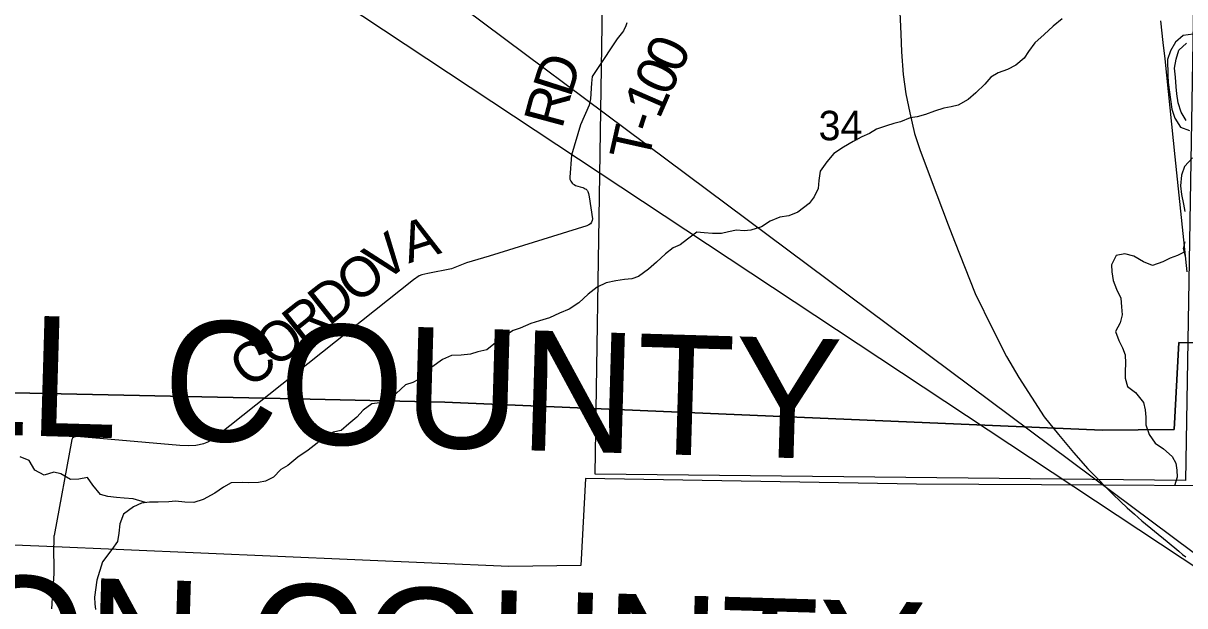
# Model space of a CAD drawing. Extents: x -19.9 to 41.9, y 0 to 32.3.
# Drawn here: x 3.386 to 5.034, y 17.59 to 18.417 of the extents above; entities that cross this region are included whole.
import ezdxf

# ---------------------------------------------------------------- set-up
doc = ezdxf.new("R2010")
doc.units = 0
for name, color, linetype in [('GM_X_Corporation', 7, 'Continuous'), ('GM_X_County', 7, 'Continuous'), ('GM_X_County_Text', 7, 'Continuous'), ('GM_X_Major_River', 7, 'Continuous'), ('GM_X_Minor_River', 7, 'Continuous'), ('GM_X_Rail_Line', 7, 'Continuous'), ('GM_X_Section', 7, 'Continuous'), ('GM_X_Section_Text', 7, 'Continuous'), ('GM_X_State_Route', 7, 'Continuous'), ('GM_X_Township_Road', 7, 'Continuous'), ('GM_X_Township_Road_Text', 7, 'Continuous'), ('SH_Text', 7, 'Continuous')]:
    doc.layers.add(name, color=color, linetype=linetype)

msp = doc.modelspace()

# ---------------------------------------------------------------- linework, layer by layer
at = {"layer": 'GM_X_Corporation'}
for points in [[(8.9, 17.8974), (8.9, 20.9), (2.1, 20.9), (2.1, 17.918), (2.4715, 17.9106), (2.973, 17.9007), (3.7505, 17.884), (3.984, 17.879), (4.2613, 17.8672), (4.9169, 17.8392), (5.0192, 17.8403), (5.0257, 17.9637), (5.4954, 17.9559), (5.761, 17.9543), (5.9048, 17.9534), (6.2397, 17.9517), (6.2497, 17.9517), (6.3069, 17.9505), (6.7, 17.9422), (6.9468, 17.937), (7.3858, 17.9277), (7.5529, 17.9242), (7.9072, 17.9171)], [(2.1, 17.918), (2.1, 14.1), (8.9, 14.1), (8.9, 17.8974), (7.9072, 17.9171), (7.5529, 17.9242), (7.3858, 17.9277), (6.9468, 17.937), (6.7, 17.9422), (6.3069, 17.9505), (6.2497, 17.9517), (6.2397, 17.9517), (5.9048, 17.9534), (5.761, 17.9543), (5.4954, 17.9559), (5.0257, 17.9637), (5.0192, 17.8403), (4.9169, 17.8392), (4.2613, 17.8672), (3.984, 17.879), (3.7505, 17.884), (2.973, 17.9007), (2.4715, 17.9106)]]:
    msp.add_lwpolyline(points, close=True, dxfattribs=at)
for points in [[(2.973, 17.9007), (3.7505, 17.884), (3.984, 17.879), (4.2613, 17.8672), (4.9169, 17.8392), (5.0192, 17.8403), (5.0257, 17.9637), (5.4954, 17.9559), (5.761, 17.9543), (5.9048, 17.9534), (6.2397, 17.9517), (6.2497, 17.9517), (6.3069, 17.9505), (6.7, 17.9422), (6.9468, 17.937), (7.3858, 17.9277), (7.5529, 17.9242), (7.9072, 17.9171), (7.9208, 18.3004), (7.9387, 18.9418), (7.9433, 19.1981), (7.9567, 19.9408), (7.9833, 20.9), (2.1, 20.9)], [(7.9012, 17.4524), (7.9072, 17.9171), (7.5529, 17.9242), (7.3858, 17.9277), (6.9468, 17.937), (6.7, 17.9422), (6.3069, 17.9505), (6.2497, 17.9517), (6.2397, 17.9517), (5.9048, 17.9534), (5.761, 17.9543), (5.4954, 17.9559), (5.0257, 17.9637), (5.0192, 17.8403), (4.9169, 17.8392), (4.2613, 17.8672), (3.984, 17.879), (3.7505, 17.884), (2.973, 17.9007), (2.4715, 17.9106), (2.1, 17.918), (2.1, 14.1)]]:
    msp.add_lwpolyline(points, dxfattribs=at)
at = {"layer": 'GM_X_County'}
msp.add_lwpolyline([(8.9, 17.6915), (8.8006, 17.694), (8.0736, 17.7036), (7.0652, 17.7237), (6.7109, 17.7307), (6.5438, 17.7343), (6.1048, 17.7436), (5.8581, 17.7488), (5.4649, 17.757), (5.4078, 17.7582), (5.3977, 17.7582), (5.0628, 17.7599), (4.9191, 17.7608), (4.6534, 17.7624), (4.1838, 17.7703), (4.1772, 17.6468), (4.0749, 17.6457), (3.4193, 17.6737), (3.142, 17.6855), (2.9085, 17.6906), (2.1311, 17.7073), (2.1, 17.7079)], dxfattribs=at)
at = {"layer": 'GM_X_Major_River'}
for points in [[(5.0461, 18.4016), (5.032, 18.3995), (5.0212, 18.3902), (5.0138, 18.3779), (5.0098, 18.3657), (5.0101, 18.3433), (5.0107, 18.3331), (5.0141, 18.3088), (5.0159, 18.2952), (5.0199, 18.282), (5.0281, 18.2696), (5.0407, 18.2649)], [(5.0359, 18.2788), (5.0289, 18.2909), (5.0249, 18.3041), (5.0231, 18.3166), (5.0218, 18.3268), (5.0208, 18.3404), (5.0195, 18.3533), (5.0219, 18.3659), (5.0255, 18.3789), (5.0364, 18.3889)], [(5.0451, 18.2258), (5.0339, 18.2135), (5.0296, 18.2013), (5.0283, 18.1861), (5.0293, 18.174), (5.0325, 18.1603), (5.0342, 18.1497)], [(5.0342, 18.1068), (5.0317, 18.0973), (5.0349, 18.086)]]:
    msp.add_lwpolyline(points, dxfattribs=at)
at = {"layer": 'GM_X_Minor_River'}
for points in [[(4.8604, 18.4235), (4.8476, 18.4128), (4.8348, 18.4009), (4.8216, 18.3894), (4.8122, 18.3768), (4.8062, 18.3672), (4.7945, 18.3573), (4.7828, 18.3515), (4.7692, 18.3464), (4.7589, 18.3406), (4.7503, 18.3303), (4.7375, 18.3184), (4.7266, 18.3085), (4.7126, 18.3008), (4.7027, 18.2984), (4.6921, 18.2964), (4.6788, 18.2921), (4.6663, 18.2875), (4.6542, 18.2843), (4.6447, 18.2827), (4.6307, 18.2769), (4.6213, 18.2746), (4.611, 18.2711), (4.5966, 18.2668), (4.5868, 18.2606), (4.5758, 18.2556), (4.5634, 18.249), (4.5498, 18.2409), (4.5362, 18.2321), (4.526, 18.2202), (4.517, 18.2069), (4.5148, 18.1939), (4.5138, 18.1822), (4.5082, 18.1707), (4.5011, 18.1608), (4.4852, 18.1489), (4.4723, 18.1435), (4.4594, 18.1414), (4.4458, 18.136), (4.4333, 18.1279), (4.4186, 18.1233), (4.4091, 18.1224), (4.3981, 18.1231), (4.3867, 18.1207), (4.3768, 18.1183), (4.3639, 18.1186), (4.3521, 18.1193), (4.3419, 18.1203), (4.3287, 18.1103), (4.3181, 18.1023), (4.3083, 18.098), (4.2973, 18.0896), (4.2845, 18.0777), (4.2732, 18.0677), (4.2592, 18.0574), (4.2494, 18.0542), (4.2391, 18.053), (4.2266, 18.051), (4.2133, 18.0482), (4.2001, 18.042), (4.1876, 18.0324), (4.1741, 18.0198), (4.1605, 18.0109), (4.1468, 18.0051), (4.1325, 17.9989), (4.1185, 17.9943), (4.106, 17.9904), (4.0912, 17.9842), (4.0813, 17.9807), (4.0674, 17.9718), (4.056, 17.9634), (4.0436, 17.9534), (4.0311, 17.9502), (4.0205, 17.9471), (4.0072, 17.9455), (3.9935, 17.945), (3.9807, 17.9395), (3.9656, 17.9288), (3.9531, 17.9146), (3.9388, 17.9069), (3.9285, 17.9034), (3.915, 17.8911), (3.9018, 17.88), (3.8919, 17.878), (3.8805, 17.8764), (3.8685, 17.8676), (3.8594, 17.8576), (3.8477, 17.848), (3.8372, 17.8385)], [(5.0332, 18.092), (5.0239, 18.0874), (5.0133, 18.0835), (5.0031, 18.0781), (4.9883, 18.0731), (4.9754, 18.0783), (4.962, 18.0861), (4.9491, 18.0894), (4.9366, 18.0874), (4.9302, 18.0741), (4.9307, 18.0642), (4.9327, 18.0517), (4.9374, 18.0396), (4.9432, 18.0264), (4.9444, 18.0142), (4.9453, 18.0029), (4.9427, 17.9918), (4.936, 17.9792), (4.9406, 17.9664), (4.9457, 17.9562), (4.9495, 17.9459), (4.95, 17.9342), (4.9494, 17.9224), (4.9494, 17.9129), (4.953, 17.9012), (4.9644, 17.8925), (4.9756, 17.8782), (4.9779, 17.868), (4.9788, 17.8577), (4.9789, 17.8467), (4.9835, 17.8331), (4.992, 17.8207), (5.0039, 17.8124), (5.0161, 17.8019), (5.0215, 17.7921), (5.0227, 17.7822), (5.0232, 17.7723), (5.0194, 17.76)], [(3.8372, 17.8385), (3.8258, 17.8365), (3.8152, 17.8318), (3.8031, 17.8207), (3.7903, 17.8107), (3.7756, 17.8007), (3.7612, 17.7892), (3.7514, 17.7834), (3.7409, 17.7723), (3.7299, 17.7665), (3.7197, 17.7649), (3.706, 17.7644), (3.6965, 17.7647), (3.6809, 17.7642), (3.6703, 17.7581), (3.6579, 17.7496), (3.6412, 17.7407), (3.628, 17.7364), (3.6151, 17.7371), (3.6021, 17.7381), (3.5923, 17.7376), (3.5775, 17.7371), (3.5649, 17.737), (3.5535, 17.7354), (3.5426, 17.7304), (3.5282, 17.72), (3.523, 17.7059), (3.5216, 17.693), (3.5198, 17.6812), (3.5117, 17.6696)], [(3.5593, 17.7362), (3.5417, 17.7414), (3.5292, 17.7424), (3.5182, 17.7434), (3.506, 17.7449), (3.4957, 17.7478), (3.4846, 17.761), (3.4773, 17.7719), (3.4648, 17.7696), (3.453, 17.7691), (3.4392, 17.7769), (3.4293, 17.7795), (3.4157, 17.7752), (3.4024, 17.7823), (3.3943, 17.7959), (3.3817, 17.8015)], [(3.5117, 17.6696), (3.4984, 17.6521), (3.4901, 17.626), (3.4869, 17.6021), (3.4874, 17.5926), (3.4886, 17.5846)]]:
    msp.add_lwpolyline(points, dxfattribs=at)
at = {"layer": 'GM_X_Rail_Line'}
msp.add_lwpolyline([(5.0376, 18.0638), (5.0204, 18.2273), (5.0061, 18.3663), (5.0035, 18.3895), (5.0003, 18.4205)], dxfattribs=at)
at = {"layer": 'GM_X_Section'}
msp.add_lwpolyline([(4.2131, 18.8031), (5.0521, 18.7876), (5.0351, 17.7675), (4.1973, 17.7768), (4.2117, 18.6878)], close=True, dxfattribs=at)
at = {"layer": 'GM_X_State_Route'}
msp.add_line((5.0311, 17.6628), (5.0355, 17.6592), dxfattribs=at)
for points in [[(4.6286, 18.4634), (4.6311, 18.4021), (4.632, 18.3762), (4.6346, 18.3442), (4.6385, 18.317), (4.6438, 18.29), (4.6507, 18.2606), (4.6583, 18.2376), (4.6743, 18.1948), (4.6982, 18.1306), (4.7074, 18.1077), (4.7368, 18.033), (4.7616, 17.9821), (4.7814, 17.9436), (4.7986, 17.9138), (4.8345, 17.8581), (4.8548, 17.8329), (4.8761, 17.8073), (4.8965, 17.7842), (4.9111, 17.7695)], [(4.9111, 17.7695), (4.9218, 17.7585), (4.9316, 17.7487), (4.9429, 17.7379), (4.9525, 17.7289), (4.963, 17.7197), (4.9734, 17.7106), (5.009, 17.6809), (5.0256, 17.6673), (5.0311, 17.6628)]]:
    msp.add_lwpolyline(points, dxfattribs=at)
at = {"layer": 'GM_X_Township_Road'}
for points in [[(4.2423, 18.4174), (4.2404, 18.4121), (4.2388, 18.4085), (4.2377, 18.4063), (4.2361, 18.4042), (4.2289, 18.3947), (4.2007, 18.3527), (4.1933, 18.3412), (4.1923, 18.3317), (4.1908, 18.3096), (4.189, 18.3008), (4.1769, 18.2728), (4.1639, 18.2296), (4.1614, 18.1984), (4.1616, 18.1958), (4.1619, 18.1948), (4.1629, 18.1927), (4.165, 18.1901), (4.1659, 18.1892), (4.1677, 18.1879), (4.1696, 18.1868), (4.1763, 18.1847), (4.1783, 18.1842)], [(4.1783, 18.1842), (4.1802, 18.1836), (4.182, 18.1829), (4.1834, 18.1821), (4.1848, 18.1812), (4.1858, 18.1803), (4.1863, 18.1797), (4.1868, 18.1791), (4.1872, 18.1783), (4.1881, 18.1753), (4.189, 18.1704), (4.1937, 18.1393), (4.1932, 18.1369), (4.1923, 18.1343), (4.1908, 18.1323), (4.1883, 18.1306), (4.1855, 18.1293), (4.0471, 18.0861), (4.0149, 18.0768), (3.9934, 18.0681), (3.9599, 18.0618), (3.9516, 18.0597), (3.9477, 18.0581), (3.9395, 18.0527), (3.6606, 17.8307), (3.6486, 17.8228), (3.6416, 17.8199), (3.6355, 17.8184), (3.631, 17.8173), (3.6209, 17.8167), (3.6079, 17.8172), (3.462, 17.83), (3.4601, 17.8297), (3.4579, 17.8291), (3.456, 17.8277), (3.4549, 17.8261), (3.4297, 17.6896)], [(3.4263, 17.5853), (3.4269, 17.5926), (3.4275, 17.6018), (3.4285, 17.616), (3.4293, 17.6282), (3.4296, 17.6361), (3.4298, 17.6436), (3.4296, 17.6507), (3.4293, 17.6627), (3.4297, 17.6896)]]:
    msp.add_lwpolyline(points, dxfattribs=at)
at = {"layer": 'SH_Text'}
msp.add_lwpolyline([(2.8043, 19.3392), (5.2749, 17.495), (2.4893, 19.3392)], close=True, dxfattribs=at)

# ---------------------------------------------------------------- texts
at = {"layer": 'GM_X_County_Text'}
for s, p in [('CARROLL COUNTY', (2.4429, 17.8593)), ('HARRISON COUNTY', (2.4348, 17.4893))]:
    msp.add_text(s, height=0.170455, rotation=358.3166, dxfattribs=at).set_placement(p)
at = {"layer": 'GM_X_Section_Text'}
msp.add_text('34', height=0.04186, rotation=0, dxfattribs=at).set_placement((4.5145, 18.2508))
at = {"layer": 'GM_X_Township_Road_Text'}
for s, rotation, p in [('0', 65.7696, (4.3174, 18.3437)), ('D', 72.258, (4.1623, 18.3101)), ('0', 65.0631, (4.3023, 18.3113)), ('R', 74.9532, (4.1504, 18.2657)), ('1', 66.4396, (4.2885, 18.2795)), ('-', 71.7057, (4.2816, 18.2587)), ('T', 77.4456, (4.2728, 18.2186)), ('A', 17.6407, (3.9328, 18.0757)), ('V', 37.3413, (3.8976, 18.0477)), ('O', 38.4365, (3.8587, 18.0168)), ('D', 38.4455, (3.8195, 17.9858)), ('R', 38.4454, (3.783, 17.9567)), ('O', 38.4445, (3.7438, 17.9256)), ('C', 38.4462, (3.7073, 17.8966))]:
    msp.add_text(s, height=0.0568, rotation=rotation, dxfattribs=at).set_placement(p)

doc.saveas('drawing.dxf')
